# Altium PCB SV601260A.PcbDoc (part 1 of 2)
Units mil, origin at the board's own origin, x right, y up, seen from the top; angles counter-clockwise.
Board outline 2250 x 2132 mil, 4 copper layers (Top Layer, GND, POWER, Bottom Layer), stack 59.6 mil thick; 105 components, 61 nets, 262 pads, 157 vias.
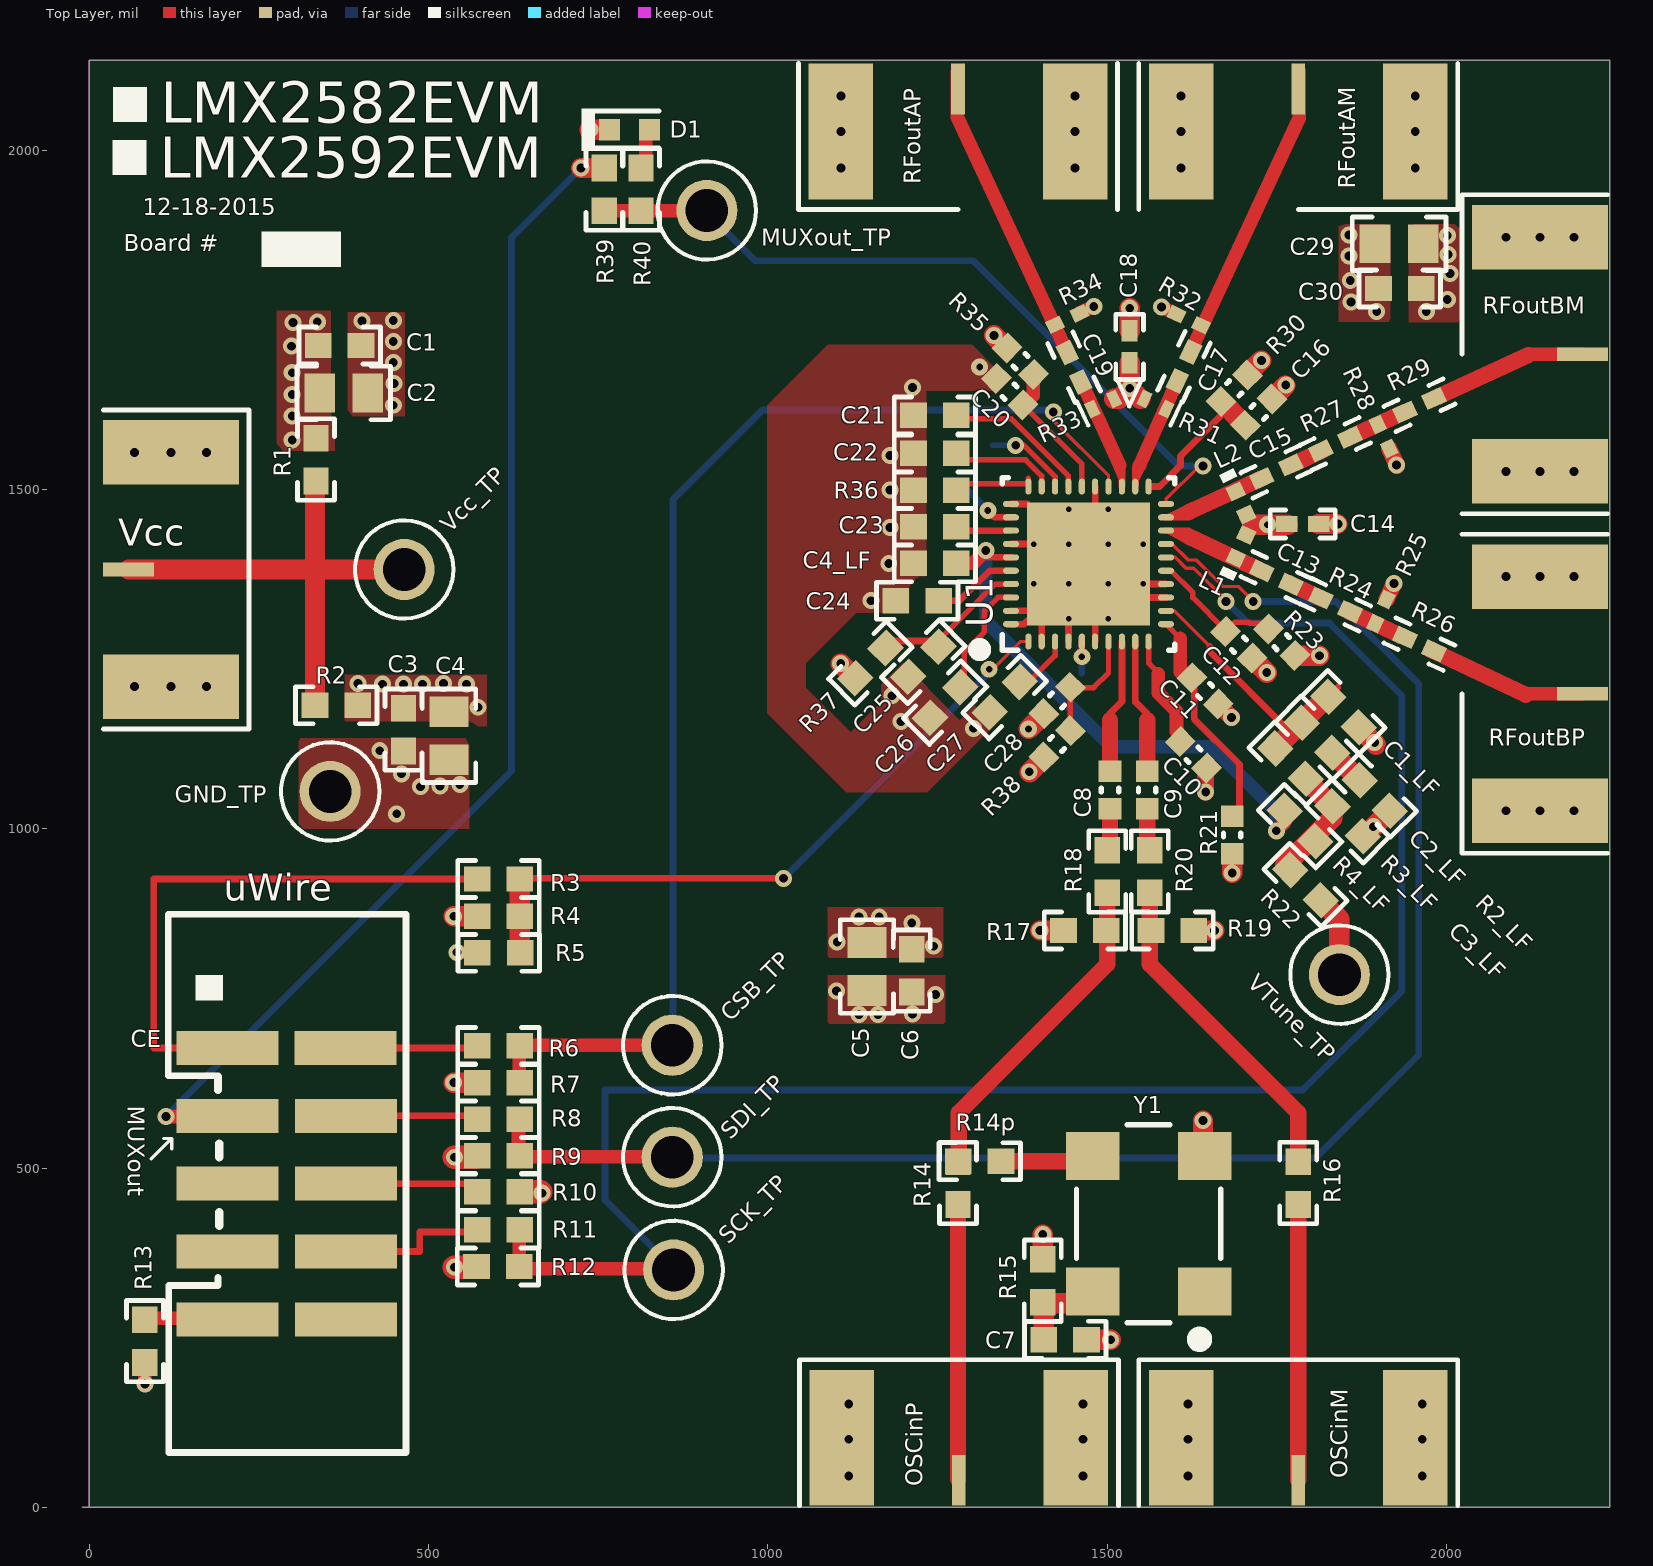
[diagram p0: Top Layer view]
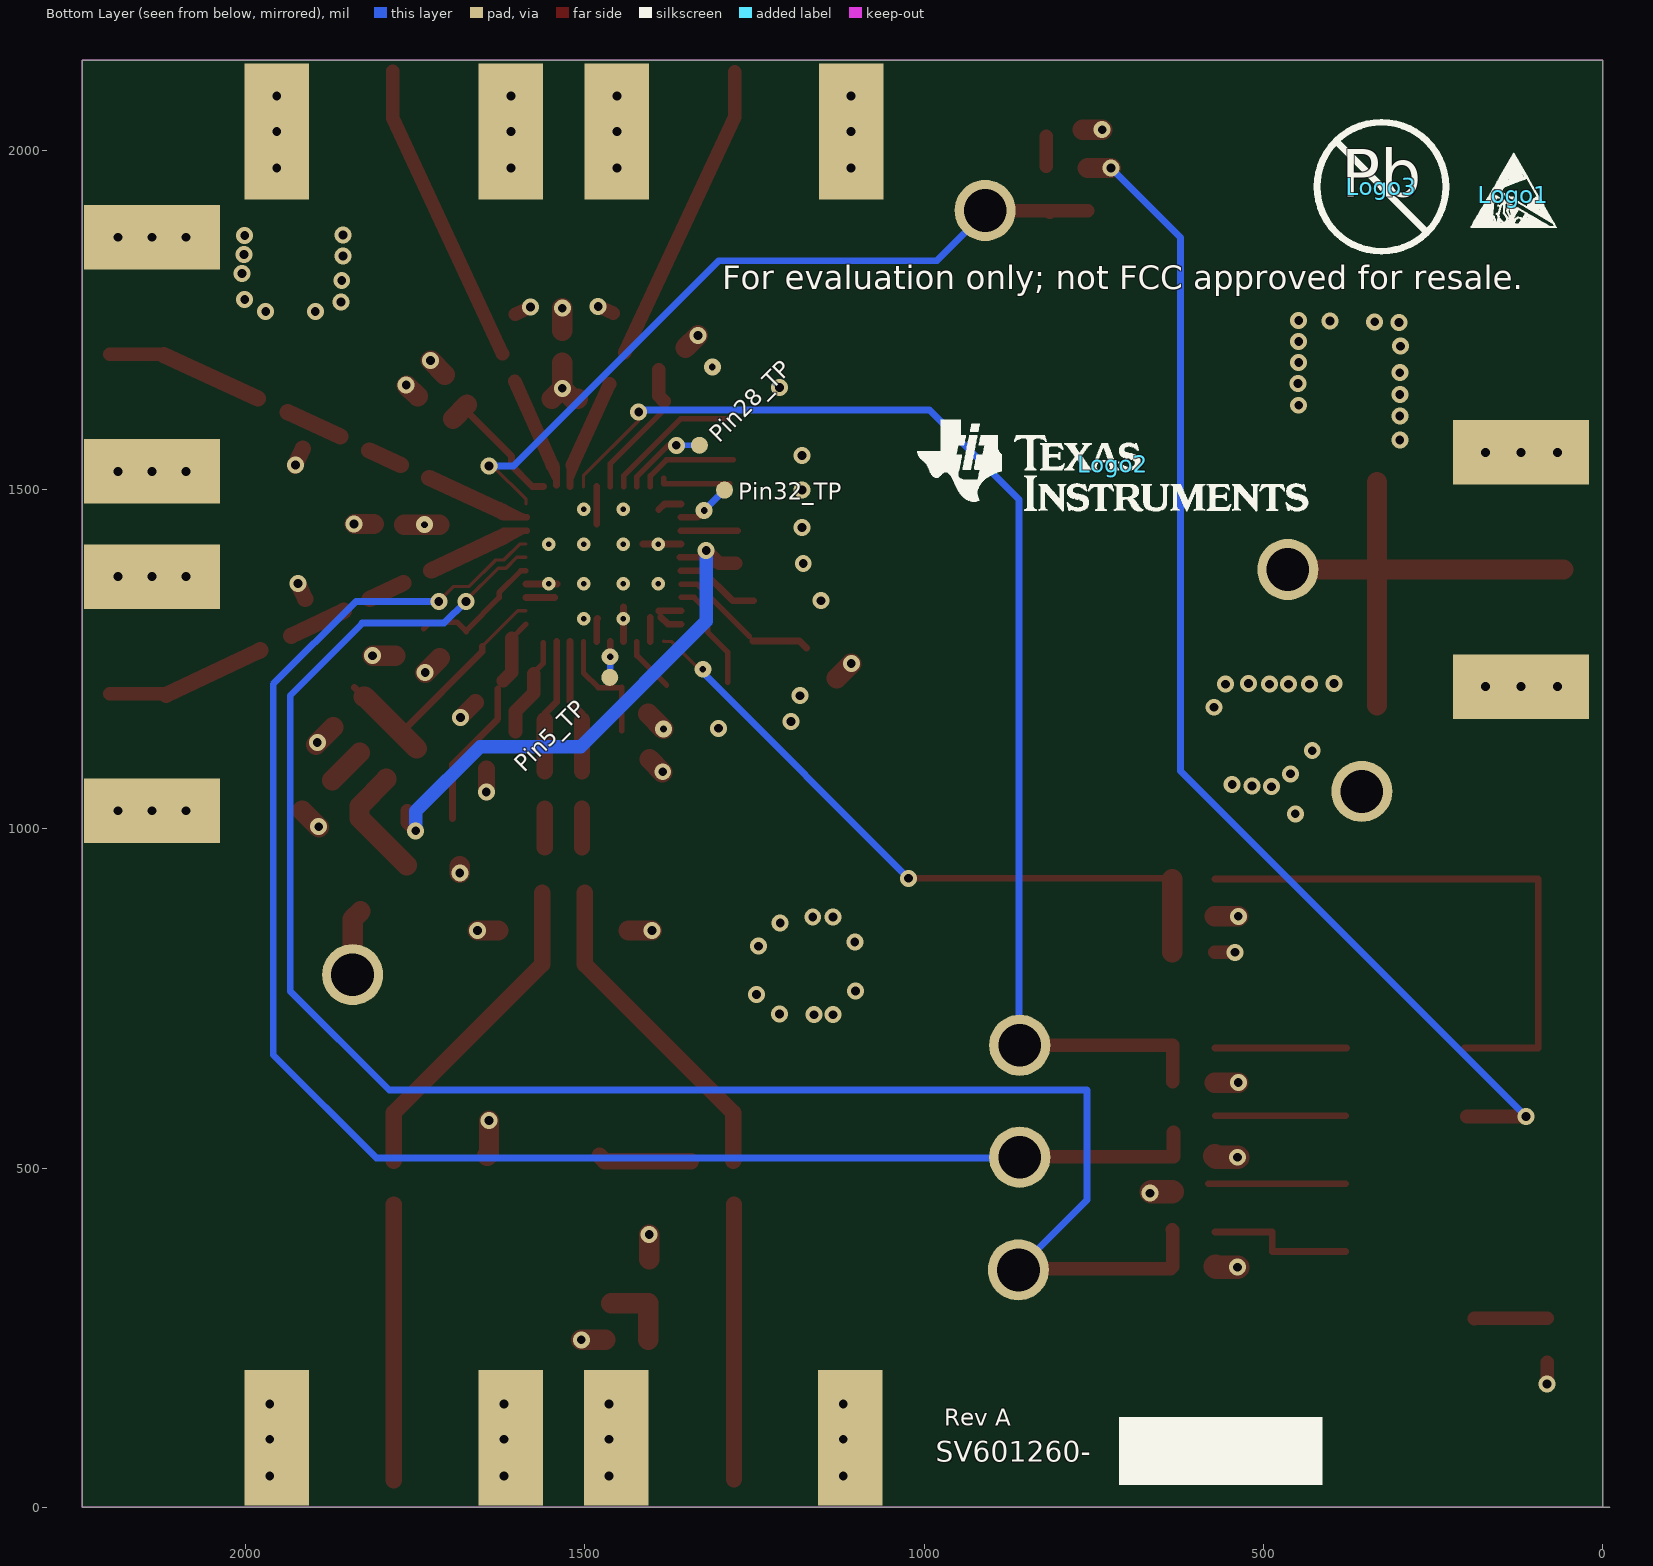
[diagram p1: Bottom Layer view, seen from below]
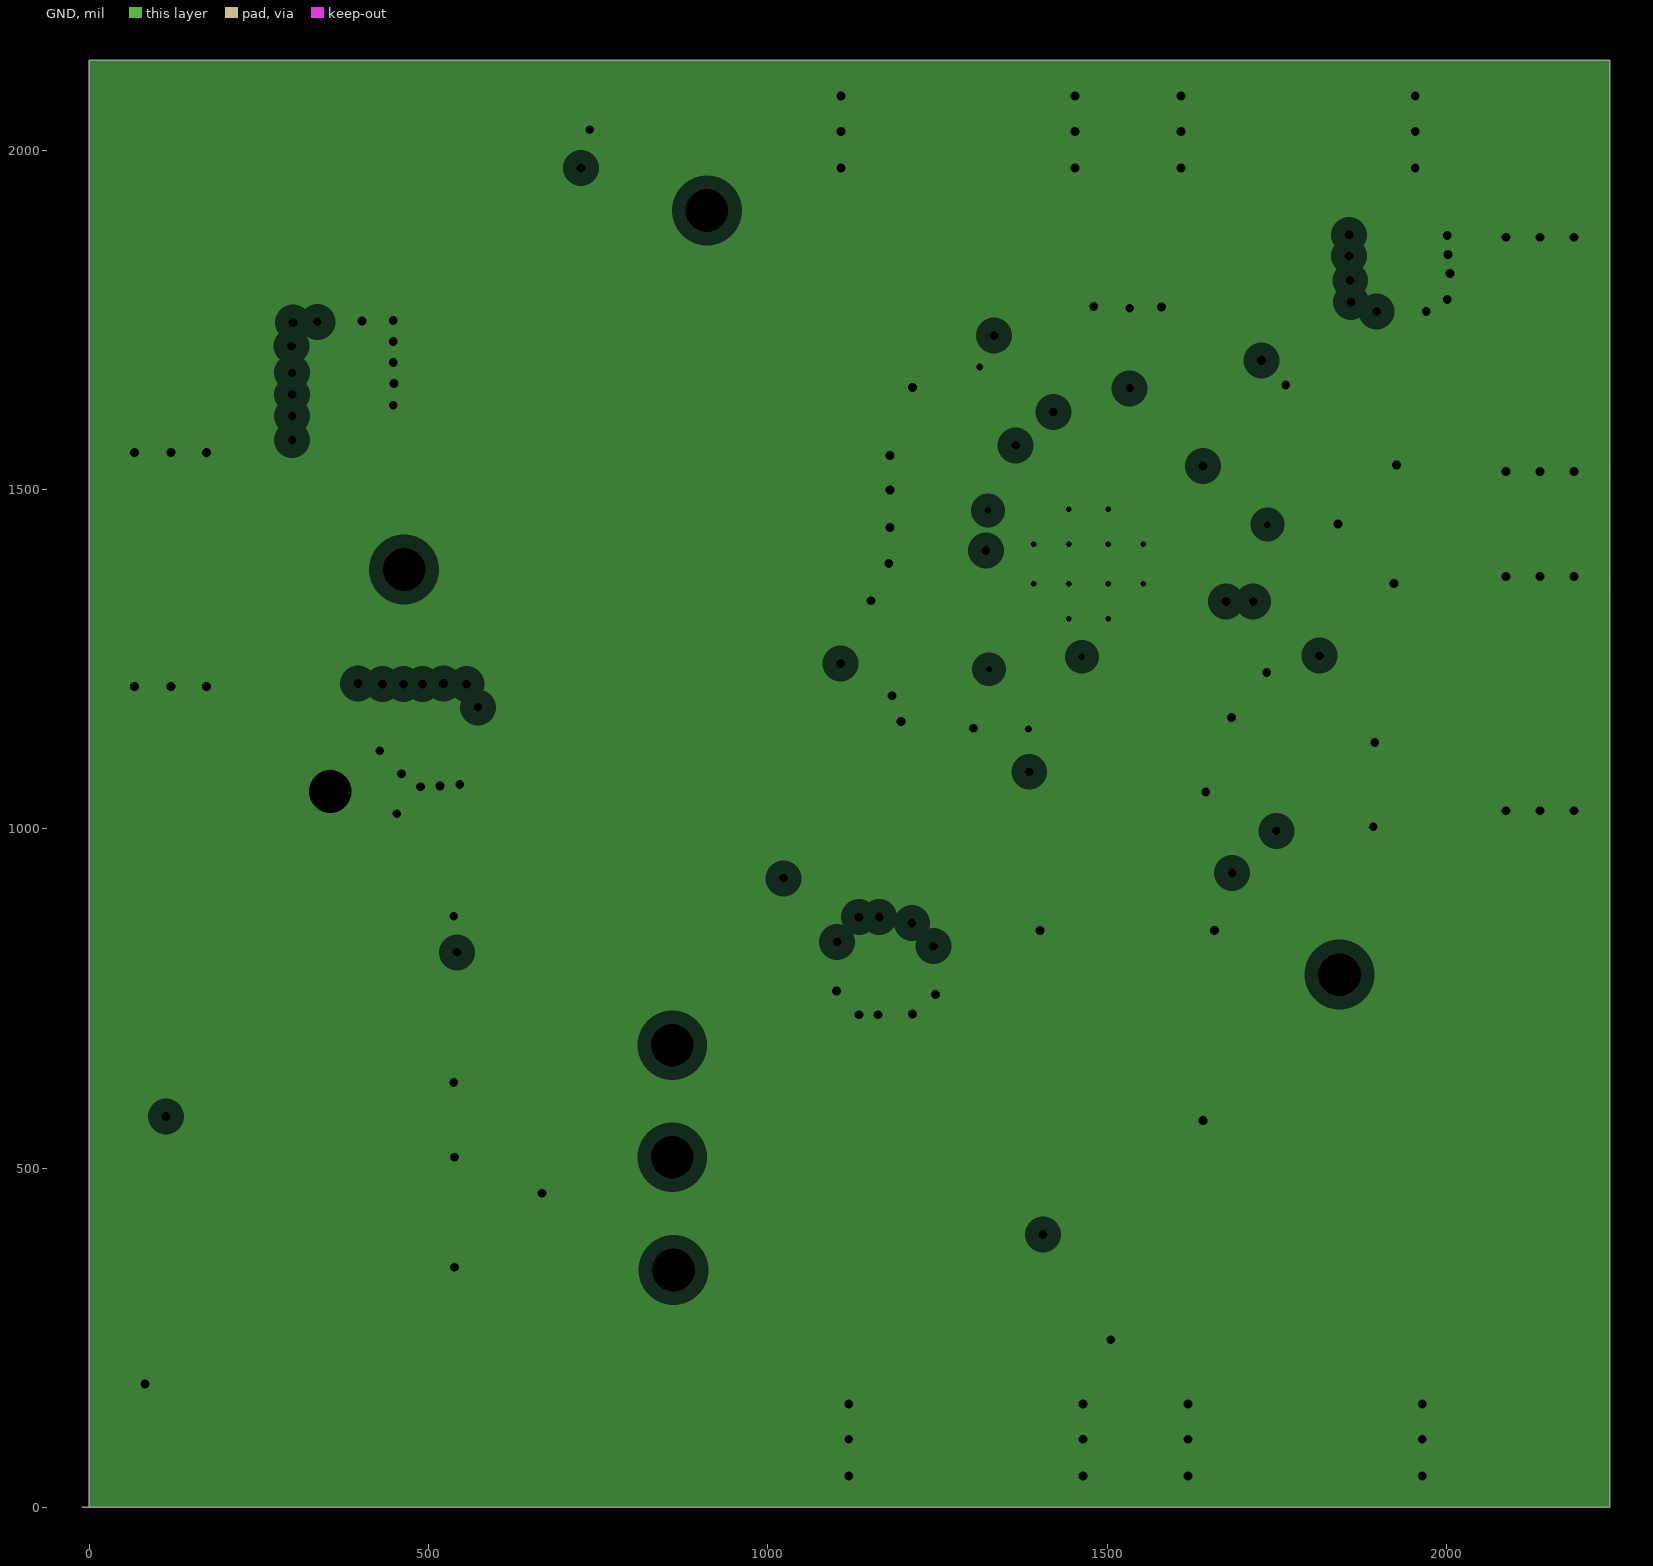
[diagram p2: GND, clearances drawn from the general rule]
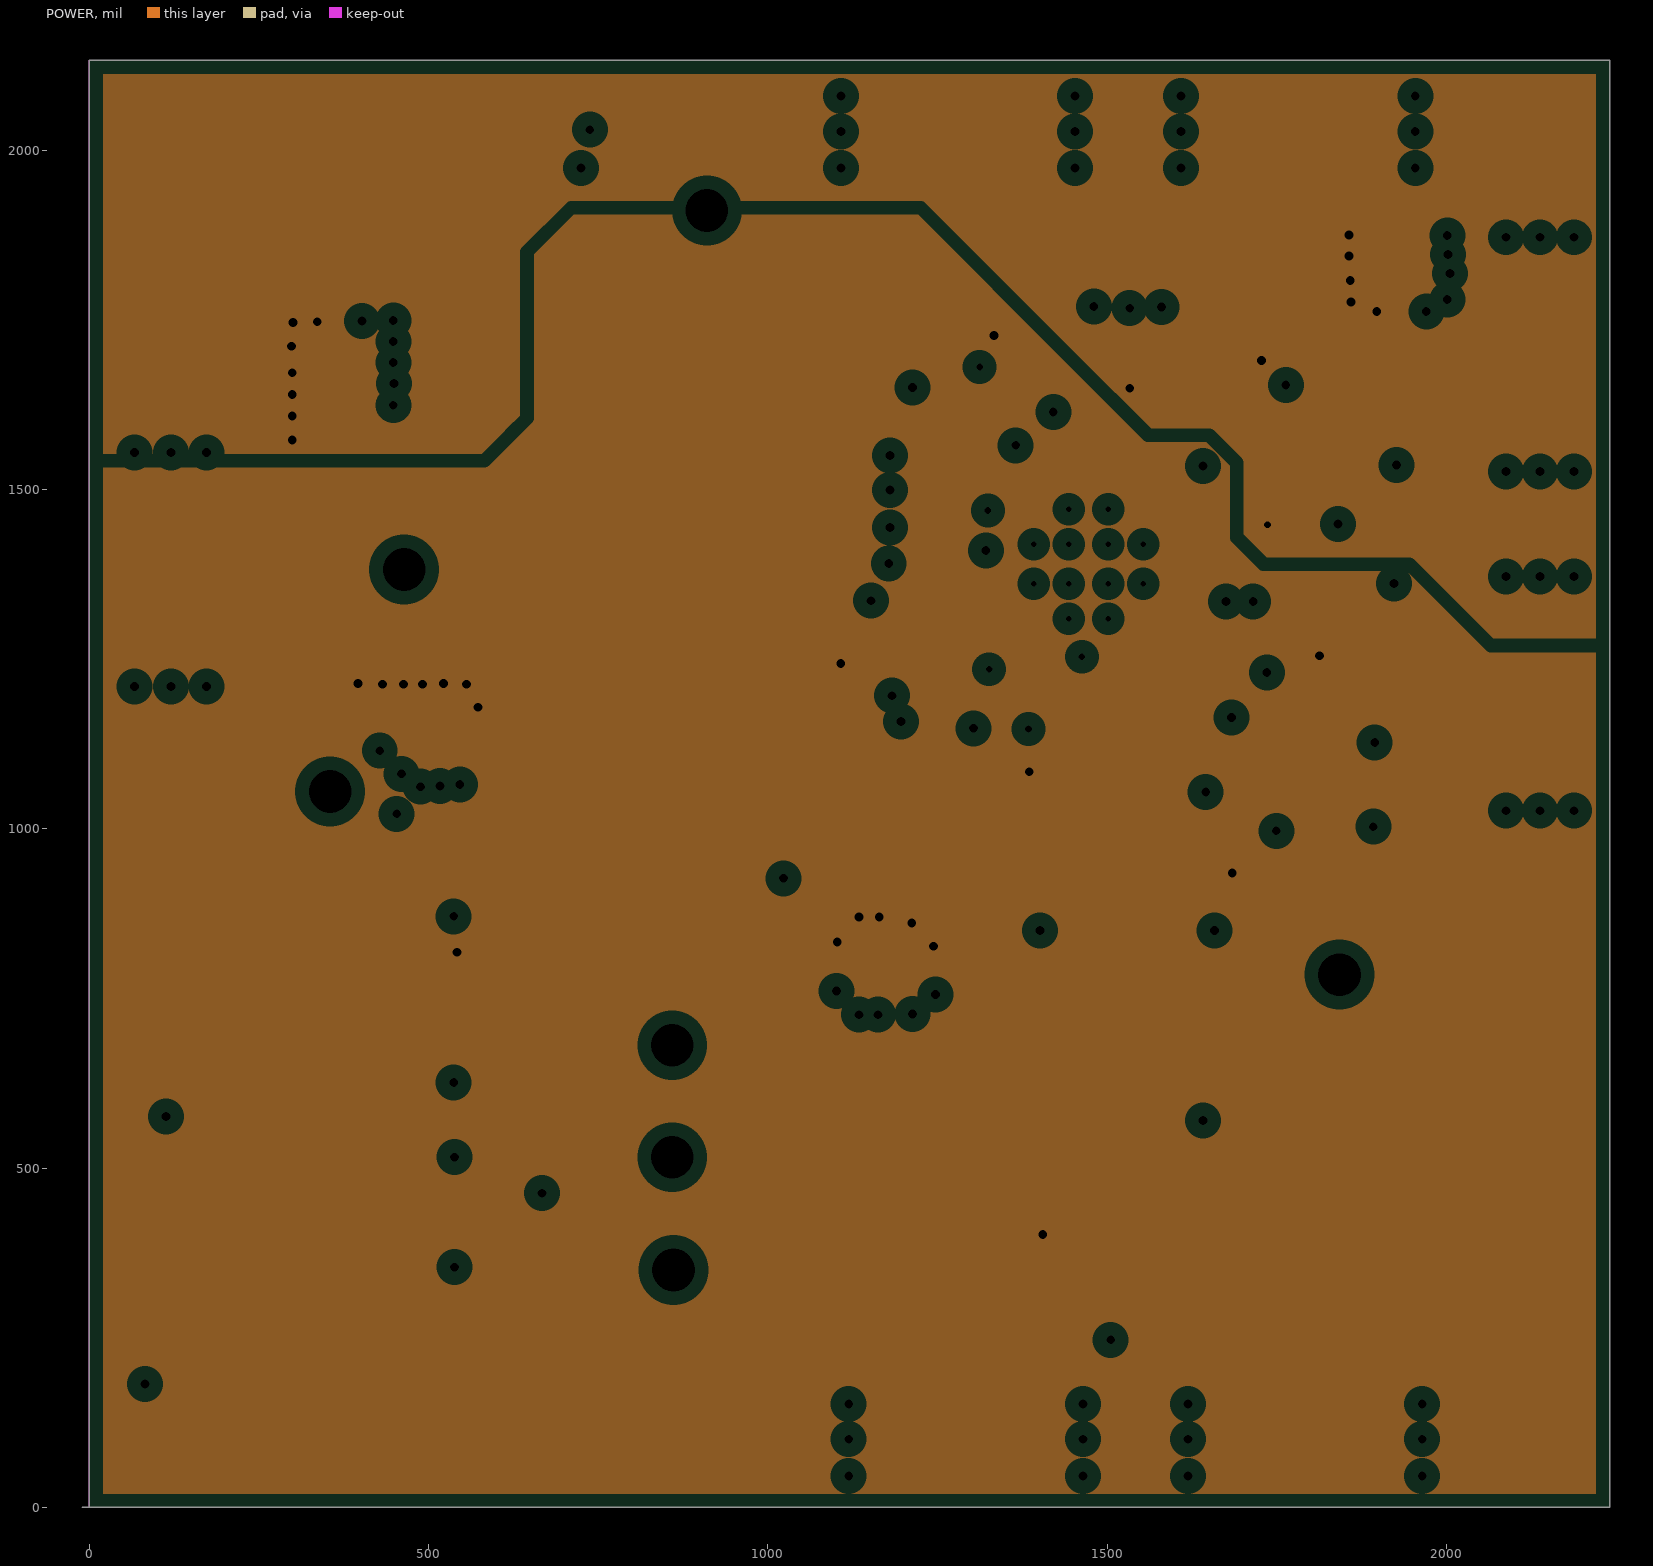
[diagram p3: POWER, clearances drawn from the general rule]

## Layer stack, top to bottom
Top Solder: solder mask 0.4, Solder Resist, Dk 3.5
Top Layer: signal copper 1.4
Dielectric1: core 9.5, Rogers4003C, Dk 4.8
GND: plane copper 1.4, net GND
Dielectric2: prepreg 35, FR-4, Dk 4.8
POWER: plane copper 1.4, net (Multiple Nets)
Dielectric3: core 9.5, FR-4, Dk 4.8
Bottom Layer: signal copper 1.4
Bottom Solder: solder mask 0.4, Solder Resist, Dk 3.5

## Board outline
2240,0 -10,0 0,0 0,2132 2240,2132 2240,0

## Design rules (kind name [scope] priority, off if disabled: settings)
AcuteAngle [All] p1: minimum=4.50000000000000E+0001 checktracksonly=FALSE
AssemblyTestPointUsage [All] p1: valid=2
Clearance Clearance_BoardEdge_MountingHoles [OnCopper and InComponentClass('Mounting Holes')] p1: gap=40
Clearance Clearance_1 [withinroom('BGA')] p2: gap=4
Clearance "pad TO PAD" [(InPadClass('All Pads')) vs (InPadClass('All Pads'))] p3: gap=7
Clearance Clearance_4 [ISPAD vs IsKeepOut] p4: gap=0
Clearance Clearance_2 [InPolygon vs InPolygon] p5: gap=25
Clearance Clearance_5 [InPolygon] p6: gap=15
Clearance [All] p7: gap=5
ComponentClearance ComponentClearance_Logo [InComponentClass('Logo')] p1: gap=50 collisioncheckmode=3 verticalgap=10 showdistances=FALSE
ComponentClearance ComponentClearance_ScrewToNut [(HasFootprint('NY PMS 440 0025 PH')) vs (HasFootprint('Keystone_1902C'))] p2: gap=5 collisioncheckmode=3 verticalgap=10 showdistances=FALSE
ComponentClearance ComponentClearance_MountingHoles [InComponentClass('Mounting Holes')] p3: gap=250 collisioncheckmode=3 verticalgap=100000 showdistances=FALSE
ComponentClearance ComponentClearance_SmallPassives [HasFootprint('0201*') or HasFootprint('0402*') or HasFootprint('0508') or HasFootprint('0603*') or HasFootprint('0612') or HasFootprint('0805*') or HasFootprint('0815*') or HasFootprint('0830*') or HasFootprint('1206*') or HasFootprint('1210*') or HasFootprint('1808*') or HasFootprint('1812*') or HasFootprint('1825*') or HasFootprint('2010*') or HasFootprint('2220*') or HasFootprint('2225*') or HasFootprint('2512*') or HasFootprint('2728*') or HasFootprint('3518*') vs HasFootprint('0201*') or HasFootprint('0402*') or HasFootprint('0508') or HasFootprint('0603*') or HasFootprint('0612') or HasFootprint('0805*') or HasFootprint('0815*') or HasFootprint('0830*') or HasFootprint('1206*') or HasFootprint('1210*') or HasFootprint('1808*') or HasFootprint('1812*') or HasFootprint('1825*') or HasFootprint('2010*') or HasFootprint('2220*') or HasFootprint('2225*') or HasFootprint('2512*') or HasFootprint('2728*') or HasFootprint('3518*')] p4: gap=5 collisioncheckmode=3 verticalgap=10 showdistances=FALSE
ComponentClearance ComponentClearance_THtoSMT [IsThruComponent vs IsSMTComponent] p5: gap=13 collisioncheckmode=3 verticalgap=30 showdistances=FALSE
ComponentClearance ComponentClearance_THtoTH [IsThruComponent vs IsThruComponent] p6: gap=13 collisioncheckmode=3 verticalgap=30 showdistances=FALSE
ComponentClearance [All] p7: gap=8 collisioncheckmode=3 verticalgap=10 showdistances=FALSE
DiffPairsRouting [All] p1: maxlimit=100 minlimit=10 mostfreqgap=10 toplayer_minwidth=15 toplayer_maxwidth=15 toplayer_prefwidth=15 bottomlayer_minwidth=15 bottomlayer_maxwidth=15 bottomlayer_prefwidth=15 maxuncoupledlength=1000
FabricationTestPointUsage TestPointUsage [All] p1: valid=2 allowmultiple=FALSE
FabricationTestpoint Testpoint [All] p1: side=3 testpointundercomponent=TRUE minsize=40 maxsize=100 preferedsize=60 minholesize=0 maxholesize=40 preferedholesize=32 testpointgrid=1 allowsidetop=TRUE allowsidebottom=TRUE usegrid=TRUE gridtolerance=0.01
FanoutControl Fanout_LCC [IsLCC] p1: bgadir=Out bgaviamode=Centered fanoutstyle=Auto fanoutdirection=Alternating viagrid=1 // Fanout_LCC (Default Rule)
FanoutControl Fanout_BGA [IsBGA] p2: bgadir=Out bgaviamode=Centered fanoutstyle=Auto fanoutdirection=Alternating viagrid=1 // Fanout_BGA (Default Rule)
FanoutControl Fanout_Default [All] p4: bgadir=Out bgaviamode=Centered fanoutstyle=Auto fanoutdirection=Alternating viagrid=1 // Fanout_Default (Default Rule)
FanoutControl Fanout_Small [(CompPinCount < 5)] p5: bgadir=Out bgaviamode=Centered fanoutstyle=Auto fanoutdirection=OutThenIn viagrid=1 // Fanout_Small (Default Rule)
HoleSize [All] p1: absolutevalues=TRUE maxlimit=251 minlimit=7.8 maxpercent=80.000 minpercent=20.000
MinimumAnnularRing MinimumAnnularRing_ThermalPadVias [IsVia and InAnyComponent] p1: minimumring=5.91
MinimumAnnularRing [All] p2: minimumring=6
MinimumSolderMaskSliver MinimumSolderMaskSliver_Logo [InComponentClass('Logo') vs InComponentClass('Logo')] p1: minsoldermaskwidth=0.7
MinimumSolderMaskSliver [All] p2: minsoldermaskwidth=0.2
PlaneClearance PlaneClearance_1 [withinroom('RF2')  or withinroom('RFvia_1')] p1: clearance=12
PlaneClearance [All] p2: clearance=20
PlaneConnect [All] p1: planeconnectstyle=Direct reliefexpansion=10 reliefentries=4 reliefconductorwidth=10 reliefairgap=10
PolygonConnect PolygonConnect-pad [ispad] p1: connectstyle=Direct reliefconductorwidth=15 reliefentries=4 polygonreliefangle="90 Angle" airgapwidth=10
PolygonConnect PolygonConnect-via [isvia] p2: connectstyle=Direct reliefconductorwidth=10 reliefentries=4 polygonreliefangle="90 Angle" airgapwidth=10
RoutingVias [All] p1: holewidth=13 width=25 viastyle="Through Hole" minholewidth=2 minwidth=5 maxholewidth=13 maxwidth=25
RoutingVias ThermalPadVias [IsVia and InAnyComponent] p2: holewidth=7.87 width=19.68 viastyle="Through Hole" minholewidth=2 minwidth=5 maxholewidth=12.99 maxwidth=23.62
SMDToCorner [All] p1: distance=30000
SilkToSilkClearance [All] p1: silktosilkclearance=0
SilkToSolderMaskClearance SilkscreenOverComponentPads [IsPad] p1: minsilkscreentomaskgap=0.9 clearancetoexposedcopper=TRUE
SolderMaskExpansion [All] p1: expansion=1.97
UnpouredPolygon [All] p1: allowunpoured=FALSE
Width 50ohm [InNetClass('50OHM')] p1: maxlimit=50 minlimit=8 preferedwidth=20
Width [All] p2: maxlimit=200 minlimit=5 preferedwidth=5 checkconnectedcopper=TRUE
14 further rules are at their usual default settings.

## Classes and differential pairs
component class Logo: Logo2
component class Header: uWire

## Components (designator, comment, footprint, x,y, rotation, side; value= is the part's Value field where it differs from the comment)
C1 "0603YC104JAT2A" 0603#1 369,1712 r180 top
C1_LF "C0603C561K5RACTU" 0603#1 1848,1172 r315 top
C2 "C0805C106K8PACTU" 0805 375,1642 r180 top
C2_LF "GRM188R71H473KA61D" 0603#1 1809,1134 r315 top
C3 "0603YC104JAT2A" 0603#1 463,1146 r90 top
C3_LF "GRM1885C2A301JA01D" 0603#1 1854,1011 r315 top
C4 "C0805C106K8PACTU" 0805 530,1137 r90 top
C4_LF "GRM188R71H682KA01D" 0603#2 1246,1391 r0 top
C5 "C0805C106K8PACTU" 0805 1146,797 r90 top
C6 "0603YC104JAT2A" 0603#1 1212,791 r90 top
C7 "C1608X7R1C105K" 0603#1 1438,247 r0 top
C8 "0603YC104JAT2A" 0603L 1504,1057 r90 top
C9 "0603YC104JAT2A" 0603L 1558.68,1057 r90 top
C10 "C1608X7R1C105K" 0603L 1627,1109 r135 top
C11 "0603YC104JAT2A" 0603L 1644,1203 r135 top
C12 "0603YC104JAT2A" 0603L 1694,1271 r135 top
C13 "GRM1535C1H101JDD5D" 0402#1 1749,1370 r155 top
C14 "GRM1535C1H101JDD5D" 0402#1 1788,1449.06 r180 top
C15 "GRM1535C1H101JDD5D" 0402#1 1749,1526 r205 top
C16 "0603YC104JAT2A" 0603L 1723,1614 r225 top
C17 "GRM1535C1H101JDD5D" 0402#1 1613,1681 r245 top
C18 "GRM1535C1H101JDD5D" 0402#2 1533,1710 r270 top
C19 "GRM1535C1H101JDD5D" 0402#1 1451,1680 r295 top
C20 "0603YC104JAT2A" 0603L 1356,1644 r315 top
C21 "C1608X5R1A106M" 0603#2 1246,1609 r180 top
C22 "C1608X5R1A106M" 0603#2 1246,1553 r180 top
C23 "C1608X5R1A106M" 0603#2 1246,1445 r180 top
C24 "C1608X5R1A106M" 0603#2 1220,1336 r180 top
C25 "0603YC104JAT2A" 0603#2 1229,1246 r45 top
C26 "C1608X5R0J105K" 0603#2 1261,1186 r225 top
C27 "C1608X5R1A106M" 0603#1 1349,1194 r45 top
C28 "0603YC104JAT2A" 0603L 1426,1189 r225 top
C29 "C0805C106K8PACTU" 0805 1930,1862 r180 top
C30 "0603YC104JAT2A" 0603#1 1931,1796 r180 top
CSB_TP "5007" Keystone5007 859,681 r270 top
D1 "LTST-C190GKT" LED_LTST-C190 796,2030 r180 top
GND_TP "5007" Keystone5007 355,1055 r270 top
L1 "LQG15HS18NJ02D" IND_LQG15H 1697,1416 r65 top
L2 "LQG15HS18NJ02D" IND_LQG15H 1697,1480 r295 top
Logo1 "ESD Susceptible" ESD_Overlay_Small 132,1934 r180 bottom
Logo2 "Texas Instruments" TI_Stacked_Overlay_Small_Vertical 722,1537 r270 bottom
Logo3 "Pb-Free Symbol" Pb-Free_Overlay_Medium 326,1946 r180 bottom
Logo4 "FCC disclaimer" FCC_disclaimer -500.95,693 r90 bottom
MUXout_TP "5007" Keystone5007 910,1911 r0 top
OSCinM "142-0701-851" EMERSON_142-0701-851 1781.34,40 r180 top
OSCinP "142-0701-851" EMERSON_142-0701-851 1281.34,40 r180 top
Pin5_TP "TESTPOINT" TP_25MIL-SMT 1463,1223 r90 bottom
Pin28_TP "TESTPOINT" TP_25MIL-SMT 1331,1565 r90 bottom
Pin32_TP "TESTPOINT" TP_25MIL-SMT 1294,1499 r90 bottom
R1 "CRCW06030000Z0EA" 0603#1 334,1544 r90 top
R2 "CRCW06030000Z0EA" 0603#1 364,1182 r0 top
R2_LF "CRCW0603150RJNEA" 0603#1 1894,1049 r315 top
R3 "CRCW060312K0JNEA" 0603#1 603,926 r0 top
R3_LF "CRCW060312R0JNEA" 0603#1 1770,1096 r315 top
R4 "CRCW060312K0JNEA" 0603#1 603,871 r0 top
R4_LF "CRCW06030000Z0EA" 0603#1 1784,1004 r315 top
R5 "CRCW060312K0JNEA" 0603#1 603.34,817.19 r0 top
R6 "CRCW060312K0JNEA" 0603#1 603,680 r0 top
R7 "CRCW060312K0JNEA" 0603#1 603,626 r0 top
R8 "CRCW060312K0JNEA" 0603#1 603,572 r180 top
R9 "CRCW060312K0JNEA" 0603#1 603,518 r0 top
R10 "CRCW06030000Z0EA" 0603#1 603,465 r180 top
R11 "CRCW060312K0JNEA" 0603#1 603,409 r0 top
R12 "CRCW060312K0JNEA" 0603#1 602,355 r0 top
R13 "CRCW06030000Z0EA" 0603#1 82,245 r270 top
R14 "CRCW060318R0JNEA" 0603#1 1280,478 r90 top
R14p "CRCW060318R0JNEA" 0603#1 1312,510 r0 top
R15 "CRCW060310R0JNEA" 0603#1 1405,334 r90 top
R16 "CRCW060318R0JNEA" 0603#1 1781.34,478 r90 top
R17 "CRCW060368R0JNEA" 0603#1 1467,850 r180 top
R18 "CRCW060318R0JNEA" 0603#1 1500,937 r90 top
R19 "CRCW060368R0JNEA" 0603#1 1596,850 r180 top
R20 "CRCW060318R0JNEA" 0603#1 1562.68,937 r270 top
R21 "CRCW06030000Z0EA" 0603L 1684,991 r90 top
R22 "CRCW06030000Z0EA" 0603#2 1792,917 r315 top
R23 "CRCW06030000Z0EA" 0603L 1757,1275 r135 top
R24 "CRCW040218R0JNED" 0402#2 1836,1330 r155 top
R25 "CRCW040268R0JNED" 0402L#1 1903,1320 r245 top
R26 "CRCW040218R0JNED" 0402#2 1960,1272 r155 top
R27 "CRCW040218R0JNED" 0402#2 1836,1567 r205 top
R28 "CRCW040268R0JNED" 0402L#1 1907,1578 r295 top
R29 "CRCW040218R0JNED" 0402#2 1960,1624 r205 top
R30 "CRCW06030000Z0EA" 0603L 1687,1649 r225 top
R31 "CRCW040249R9FKED" 0402L#2 1571,1626 r155 top
R32 "CRCW040249R9FKED" 0402L#1 1620,1750 r155 top
R33 "CRCW040249R9FKED" 0402L#2 1494,1626 r205 top
R34 "CRCW040249R9FKED" 0402L#1 1441,1751 r205 top
R35 "CRCW06030000Z0EA" 0603L 1372,1689 r135 top
R36 "RC0603FR-07680RL" 0603#2 1246,1499 r180 top
R37 "CRCW06030000Z0EA" 0603#2 1151,1244 r225 top
R38 "CRCW06030000Z0EA" 0603L 1426,1125 r45 top
R39 "CRCW06030000Z0EA" 0603#1 759,1942 r270 top
R40 "RC0603JR-07330RL" 0603#1 813,1942 r270 top
RFoutAM "142-0701-851" EMERSON_142-0701-851 1781.34,2090 r0 top locked
RFoutAP "142-0701-851" EMERSON_142-0701-851 1280,2090 r0 top locked
RFoutBM "142-0701-851" EMERSON_142-0701-851 2200,1699.06 r270 top
RFoutBP "142-0701-851" EMERSON_142-0701-851 2200,1199.06 r270 top
SCK_TP "5007" Keystone5007 861,350 r270 top
SDI_TP "5007" Keystone5007 859,516 r270 top
U1 "LMX2582RHAR" RHA0040C 1472.28,1390 r90 top
uWire "52601-S10-8LF" FCI_52601-S10-8LF 291,477 r0 top
Vcc "142-0701-851" EMERSON_142-0701-851 58,1382 r90 top
Vcc_TP "5007" Keystone5007 464,1382 r90 top
VTune_TP "5007" Keystone5007 1842,785 r0 top (schematic designator Vtune_TP)
Y1 "CWX813-100.0M" OSC_CWX 1561,418 r180 top

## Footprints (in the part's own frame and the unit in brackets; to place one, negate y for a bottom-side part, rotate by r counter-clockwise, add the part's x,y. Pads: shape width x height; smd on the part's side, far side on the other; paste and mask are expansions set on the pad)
0402#1 [mm] "0402 from SM-752 data"
  rect 0.8x0.6 smd mask+0: 1(-0.6,0) 2(0.6,0)
  silkscreen extent -1.22,-0.52 1.22,0.52, body extent -0.55,-0.3 0.55,0.3, height 0.6
0402#2 [mm] "0402 from SM-752 data"
  rect 0.8x0.6 smd: 1(-0.6,0) 2(0.6,0)
  silkscreen extent -1.22,-0.52 1.22,0.52, body extent -0.55,-0.3 0.55,0.3, height 0.6
0402L#1 [mm] "0402 from SM-752 data"
  rect 0.6x0.5 smd: 1(-0.5,0) 2(0.5,0)
  body extent -0.55,-0.3 0.55,0.3, height 0.6
0402L#2 [mm] "Chip Capacitor, Body 1.0x0.5mm, IPC High Density"
  rect 0.4x0.6 smd mask+0: 1(-0.45,0) 2(0.45,0)
  silkscreen extent -0.85,-0.5 0.85,0.5, body extent -0.55,-0.3 0.55,0.3, height 1.3
0603#1 [mm] "0603 from SM-752 data"
  rect 1x0.95 smd mask+0: 1(-0.8,0) 2(0.8,0)
  silkscreen extent -1.52,-0.69 1.52,0.69, body extent -0.87,-0.47 0.87,0.47, height 0.85
0603#2 [mm] "0603 from SM-752 data"
  rect 1x0.95 smd: 1(-0.8,0) 2(0.8,0)
  silkscreen extent -1.52,-0.69 1.52,0.69, body extent -0.87,-0.47 0.87,0.47, height 0.85
0603L [mm] "0603 from SM-752 data"
  rect 0.8x0.85 smd: 1(-0.7,0) 2(0.7,0)
  silkscreen extent -0.07,-0.33 0.07,0.33, body extent -0.87,-0.47 0.87,0.47, height 0.85
0805 [mm] "0805"
  rect 1.15x1.45 smd mask+0: 1(-0.9,0) 2(0.9,0)
  silkscreen extent -1.75,-1 1.75,1, body extent -1.1,-0.72 1.1,0.72, height 1.1
EMERSON_142-0701-851 [mil] "Johnson Components"
  rect 20x75 smd mask+0: 1(0,0)
  rect 95x200 smd mask+0: 2(-172.5,-62.5) 3(172.5,-62.5)
  rect 95x200 smd far side mask+0: 4(172.5,-62.5) 5(-172.5,-62.5)
  silkscreen extent -235,-178 235,38, body extent -190,-158 190,424, height 155
ESD_Overlay_Small [mil]
  silkscreen extent -62,-48 64,61
FCC_disclaimer [mil]
FCI_52601-S10-8LF [mil] "FCI Electronics"
  rect 150x50 smd mask+0: 1(-87.5,200) 2(86.5,200) 3(-87.5,100) 4(87.5,100) 5(-87.5,0) 6(87.5,0) 7(-87.5,-100) 8(87.5,-100) 9(-87.5,-200) 10(87.5,-200)
  silkscreen extent -175,-396 176,397, body extent -173,-395 172,395, height 496
IND_LQG15H [mm] "MuRata"
  rect 0.55x0.6 smd: 1(-0.475,0) 2(0.475,0)
  silkscreen extent -1.3,-0.3 -0.95,0.3, body extent -0.52,-0.27 0.52,0.27, height 0.55
Keystone5007 [mil]
  round 90 hole 63 mask+0: 1(0,0)
  silkscreen extent -72,-72 72,72
LED_LTST-C190 [mm] "Lite-On"
  rect 0.8x0.8 smd: 1(-0.75,0) 2(0.75,0)
  silkscreen extent -1.1,-0.8 1.8,0.8, body extent -0.85,-0.45 0.85,0.45, height 0.9
OSC_CWX [mm] "CONNOR WINFIELD"
  rect 2x1.8 smd mask+0: 1(-2.1,2.54) 2(-2.1,-2.54) 3(2.1,-2.54) 4(2.1,2.54)
  silkscreen extent -2.7,-3.7 2.7,4.55, body extent -2.65,-3.65 2.65,3.65, height 1.31
Pb-Free_Overlay_Medium [mil]
  silkscreen extent -95,-95 95,95
RHA0040C [mm] "QFN, 40-Leads, Body 6x6mm, Pitch 0.5mm, Thermal Pad 4.6 x 4.6mm, TI Recommended"
  oval 0.6x0.23 smd: 1(-2.9,2.25) 2(-2.9,1.75) 3(-2.9,1.25) 4(-2.9,0.75) 5(-2.9,0.25) 6(-2.9,-0.25) 7(-2.9,-0.75) 8(-2.9,-1.25) 9(-2.9,-1.75) 10(-2.9,-2.25) 21(2.9,-2.25) 22(2.9,-1.75) 23(2.9,-1.25) 24(2.9,-0.75) 25(2.9,-0.25) 26(2.9,0.25) 27(2.9,0.75) 28(2.9,1.25) 29(2.9,1.75) 30(2.9,2.25)
  oval 0.23x0.6 smd: 11(-2.25,-2.9) 12(-1.75,-2.9) 13(-1.25,-2.9) 14(-0.75,-2.9) 15(-0.25,-2.9) 16(0.25,-2.9) 17(0.75,-2.9) 18(1.25,-2.9) 19(1.75,-2.9) 20(2.25,-2.9) 31(2.25,2.9) 32(1.75,2.9) 33(1.25,2.9) 34(0.75,2.9) 35(0.25,2.9) 36(-0.25,2.9) 37(-0.75,2.9) 38(-1.25,2.9) 39(-1.75,2.9) 40(-2.25,2.9)
  rect 4.6x4.6 smd paste-2.5: 41(0,0)
  silkscreen extent -3.22,-3.22 3.22,3.22, body extent -3.08,-3.08 3.08,3.08, height 1.01
TI_Stacked_Overlay_Small_Vertical [mil]
  silkscreen extent -66,-288 69,288
TP_25MIL-SMT [mil]
  round 25 smd mask-2.5: 1(0,0)

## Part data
C1 C3 C6 C8 C9 C11 C12 C16 C20 C25 C28 C30: "CAP, CERM, 0.1uF, 16V, +/-5%, X7R, 0603"
C1_LF: "CAP, CERM, 560 pF, 50 V, +/- 10%, X7R, 0603"
C2 C4 C5 C29: "CAP, CERM, 10uF, 10V, +/-10%, X5R, 0805"
C2_LF: "CAP, CERM, 0.047 µF, 50 V, +/- 10%, X7R, 0603"
C3_LF: "CAP, CERM, 300pF, 100V, +/-5%, C0G/NP0, 0603"
C4_LF: "CAP, CERM, 6800 pF, 50 V, +/- 10%, X7R, 0603"
C7 C10: "CAP, CERM, 1uF, 16V, +/-10%, X7R, 0603"
C13 C14 C15 C17 C18 C19: "CAP, CERM, 100 pF, 50 V, +/- 5%, C0G/NP0, 0402"
C21 C22 C23 C24 C27: "CAP, CERM, 10uF, 10V, +/-10%, C0G/NP0, 0603"
C26: "CAP, CERM, 1 µF, 6.3 V, +/- 10%, X5R, 0603"
CSB_TP GND_TP MUXout_TP SCK_TP SDI_TP Vcc_TP VTune_TP: "Test Point, Compact, White, TH"
D1: "LED, Green, SMD"
L1 L2: "Inductor, Multilayer, Air Core, 18 nH, 0.3 A, 0.36 ohm, SMD"
Logo1: library part ESD_Susceptible, "ESD Susceptible Symbol"
Logo2: library part TI_Logo, "Texas Instrument Corporate Signature"
Logo3: library part Pb-Free
Logo4: library part FCC_disclaimer, "FCC_disclaimer"
OSCinM OSCinP RFoutAM RFoutAP RFoutBM RFoutBP Vcc: "Connector, SMT, End launch SMA 50 ohm"
Pin5_TP Pin28_TP Pin32_TP: "TEST POINT.  No entry in BOM."
R1 R2 R4_LF R10 R13 R21 R22 R23 R30 R35 R37 R38 R39: "RES, 0 ohm, 5%, 0.1W, 0603"
R2_LF: "RES, 150, 5%, 0.1 W, 0603"
R3 R4 R5 R6 R7 R8 R9 R11 R12: "RES, 12k ohm, 5%, 0.1W, 0603"
R3_LF: "RES, 12, 5%, 0.1 W, 0603"
R14 R14p R16 R18 R20: "RES, 18 ohm, 5%, 0.1W, 0603"
R15: "RES, 10 ohm, 5%, 0.1W, 0603"
R17 R19: "RES, 68 ohm, 5%, 0.1W, 0603"
R24 R26 R27 R29: "RES, 18, 5%, 0.063 W, 0402"
R25 R28: "RES, 68, 5%, 0.063 W, 0402"
R31 R32 R33 R34: "RES, 49.9, 1%, 0.063 W, 0402"
R36: "RES, 680, 1%, 0.1 W, 0603"
R40: "RES, 330 ohm, 5%, 0.1W, 0603"
U1: "High Performance, Wideband PLLatinum RF Synthesizer, RHA0040C"
uWire: "Header (shrouded), 100mil, 5x2, Gold plated, SMD"
Y1: "OSC 100.0000MHZ 3.3V +-25PPM SMD"

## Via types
v1: diameter 25, hole 13, Top Layer to Bottom Layer, tented both sides, 74 vias
v2: diameter 25, hole 13, Top Layer to Bottom Layer, 65 vias
v3: diameter 19.68, hole 7.87, Top Layer to Bottom Layer, 12 vias
v4: diameter 25, hole 10, Top Layer to Bottom Layer, 6 vias

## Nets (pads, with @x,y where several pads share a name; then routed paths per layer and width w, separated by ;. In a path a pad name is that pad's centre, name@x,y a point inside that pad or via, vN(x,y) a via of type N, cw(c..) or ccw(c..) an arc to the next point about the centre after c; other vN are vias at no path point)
GND: C1.1 C1_LF.2 C2.1 C3.1 C3_LF.2 C4.1 C4_LF.1 C5.1 C6.1 C7.2 C10.1 C11.1 C12.1 C14.1 C16.1 C18.1 C20.1 C21.2 C22.2 C23.2 C24.2 C25.1 C26.2 C27.1 C28.2 C29.1 C30.1 D1.2 GND_TP.1 OSCinM.2 OSCinM.3 OSCinM.4 OSCinM.5 OSCinP.2 OSCinP.3 OSCinP.4 OSCinP.5 R2_LF.2 R4.1 R7.1 R9.1 R10.1 R12.1 R13.2 R17.2 R19.1 R25.1 R28.2 R32.2 R34.1 R36.2 RFoutAM.2 RFoutAM.3 RFoutAM.4 RFoutAM.5 RFoutAP.2 RFoutAP.3 RFoutAP.4 RFoutAP.5 RFoutBM.2 RFoutBM.3 RFoutBM.4 RFoutBM.5 RFoutBP.2 RFoutBP.3 RFoutBP.4 RFoutBP.5 U1.2 U1.4 U1.6 U1.13 U1.14 U1.25 U1.31 U1.34 U1.39 U1.40 U1.41 Vcc.2 Vcc.3 Vcc.4 Vcc.5 Y1.2 | length 1190.2
  Top Layer w10: U1.40@1358.11,1301.42 1377.42,1301.42 U1.41@1388,1312 ; U1.39@1358.11,1321.1 1390.9,1321.1 U1.41@1391,1321 ; U1.34@1358.11,1419.53 U1.41@1414.47,1419.53 ; U1.31@1358.11,1478.58 1382.42,1478.58 U1.41@1391,1470 ; U1.2@1403.39,1275.83 U1.41@1403.39,1311.61 ; U1.4@1442.76,1275.83 U1.41@1442.76,1326.76 ; U1.41@1481,1310 1482.13,1308.87 U1.6@1482.13,1275.83 ; U1.41@1482.13,1449.13 U1.25@1482.13,1504.17 ; U1.41@1540.53,1360.47 U1.14@1586.46,1360.47 ; U1.41@1544.21,1340.79 U1.13@1586.46,1340.79
  Top Layer w20: v1(82,182) R13.2@82,214 ; R34.1@1457.84,1759.32 v2(1480.13,1769.71) ; v2(1579.87,1768.71) R32.2@1602.16,1758.32
  Top Layer w24: R25.1@1911.81,1338.43 v2(1922.55,1361.21) ; R28.2@1915.54,1559.85 v2@1927,1535
  Top Layer w25: v1(1645,1054) C10.1@1645,1088 ; C11.1@1660.81,1186.19 v2(1683,1164)
  Top Layer w30: v2(537,626) R7.1@571.5,626 ; v2(537,871) R4.1@571.5,871 ; v2(737.53,2030) D1.2@766,2030 ; v4(1384,1147) C28.2@1406.51,1169.51 ; v1(1401,850) R17.2@1435.5,850 ; C7.2@1469.5,247 v2(1505,247) ; C18.1@1533,1734 v2(1533,1767) ; R19.1@1627.5,850 v1(1658,850) ; v2(1641,570) 1641,520.68 Y1.2@1643.68,518 ; C12.1@1713.49,1251.51 v2(1735,1230) ; C16.1@1746,1637 v1@1762,1653 ; C14.1@1810.62,1449 v1@1839,1449 ; C1_LF.2@1870.27,1149.73 v2@1896,1124 ; v2@1891.54,1002 R2_LF.2@1916.27,1026.73
  Top Layer w35: v2(538,354) 569.5,354 R12.1@570.5,355 ; v2(538,516) 569.5,516 R9.1@571.5,518 ; R10.1@634.5,465 v2@665,465
  other v1: 1119,46.5 1619,46.5 1464,46.5 1964,46.5 1119,100.5 1619,100.5 1464,100.5 1964,100.5 1119,152.5 1619,152.5 1464,152.5 1964,152.5 1162,726 1213,727 2087.5,1026.56 2137.5,1026.56 2187.5,1026.56 517,1063 546,1065 460,1081 66.5,1209.5 120.5,1209.5 172.5,1209.5 2087.5,1371.56 2137.5,1371.56 2187.5,1371.56 1840,1449 2087.5,1526.56 2137.5,1526.56 2187.5,1526.56 66.5,1554.5 120.5,1554.5 172.5,1554.5 448,1624 1763,1654 449,1656 448,1718 2087.5,1871.56 2137.5,1871.56 2187.5,1871.56 1107.5,1973.5 1608.84,1973.5 1953.84,1973.5 1452.5,1973.5 1107.5,2027.5 1608.84,2027.5 1953.84,2027.5 1452.5,2027.5 1107.5,2079.5 1608.84,2079.5 1953.84,2079.5 1452.5,2079.5
  other v2: 667,463 1134,726 1247,756 1101,761 1892,1003 453,1022 488,1062 428,1115 1894,1127 1303.04,1148.04 1196,1158 1183,1196 1152,1336 1178,1391 1180,1444 1180,1499 1926,1536 1180,1550 1213,1650 448,1687 402,1748 448,1749 1970,1762 2001,1780 2005,1818 2002,1846 2001,1874
  other v3: 1443.17,1309.29 1501.4,1309.29 1391.58,1360.89 1443.17,1360.89 1501.4,1360.89 1552.99,1360.89 1391.58,1419.11 1443.17,1419.11 1501.4,1419.11 1552.99,1419.11 1443.17,1470.71 1501.4,1470.71
  other v4: 1312,1680.49
MUXOUT: R39.1 uWire.3 | length 1772.3
  Top Layer w20: v2(113,576) uWire.3@200,576
  Top Layer w30: v2(724.5,1973.5) R39.1@759,1973.5
  Bottom Layer w10: v2(113,576) 622,1085 622,1870.99 v2(724.5,1973.5)
NetC1_LF_1: C1_LF.1 C2_LF.1 R3_LF.1 U1.12 | length 388.5
  Top Layer w5: U1.12@1586.46,1321.1 1598.9,1321.1 1651,1269
  Top Layer w10: 1651,1269 1651,1261 1768,1144 ; C1_LF.1@1825.73,1194.27 1839.46,1208
  Top Layer w30: R3_LF.1@1747.73,1118.27 1823.73,1194.27 C1_LF.1@1825.73,1194.27
NetC2_LF_2: C2_LF.2 R2_LF.1 | length 57.2
  Top Layer w30: C2_LF.2@1831.27,1111.73 R2_LF.1@1871.73,1071.27
NetC3_LF_1: C3_LF.1 R3_LF.2 R4_LF.2 R22.1 | length 173
  Top Layer w30: R22.1@1762,946 1831.73,1015.73 C3_LF.1@1831.73,1033.27 1792.27,1072.73 R3_LF.2@1792.27,1073.73
NetC4_LF_2: C4_LF.2 R4_LF.1 U1.35 | length 811.9
  Top Layer w10: 1311,1400 U1.35@1360,1400
  Top Layer w20: C4_LF.2@1277.5,1391 1302,1391 1311,1400 v2(1321,1410) ; v2(1749,997) 1761.73,1009.73 R4_LF.1@1761.73,1026.27
  Bottom Layer w20: v2(1321,1410) 1321,1321 1321,1306 1506,1121 1654,1121 1749,1026 v2(1749,997)
NetC7_1: C7.1 R15.1 Y1.4 | length 108.8
  Top Layer w30: C7.1@1406.5,247 1406.5,301 Y1.4@1461.32,301
NetC8_1: C8.1 R18.2 | length 56.9
  Top Layer w24: R18.2@1504,972.5 C8.1@1504,1029.44
NetC8_2: C8.2 U1.8 | length 188.5
  Top Layer w10: 1504,1170 1521.5,1187.5 U1.8@1521.5,1275.83
  Top Layer w24: C8.2@1504,1084.56 1504,1160
NetC9_1: C9.1 R20.1 | length 56.9
  Top Layer w24: R20.1@1558.68,972.5 C9.1@1558.68,1029.44
NetC9_2: C9.2 U1.9 | length 188.5
  Top Layer w10: 1541.18,1187.5 U1.9@1541.18,1275.83 ; 1541.5,1186.5 1559,1169
  Top Layer w24: C9.2@1558.68,1084.56 1558.68,1160
NetC10_2: C10.2 U1.10 | length 138.8
  Top Layer w8: U1.10@1560.87,1273.86 1560.87,1244.13 1570,1235
  Top Layer w20: 1575,1228 1575,1200 1602,1173 C10.2@1602,1143
NetC11_2: C11.2 R21.2 U1.11 | length 316.1
  Top Layer w8: U1.11@1586.46,1301.42 1607.5,1280.37
  Top Layer w10: C11.2@1628,1206 1628,1162 1695,1095 R21.2@1695,1015
  Top Layer w20: 1607.5,1280.37 1607.5,1230.5 C11.2@1620.01,1217.99
NetC12_2: C12.2 R23.2 U1.15 | length 203.5
  Top Layer w8: U1.15@1586.46,1380.16 1593.98,1380.16 1626,1348.14 1626,1340.61 1674.51,1292.1 C12.2@1674.51,1290.49 1688.47,1304.44 1708.56,1304.44 1710,1303 1729,1303 R23.2@1737.51,1294.49
NetC13_1: C13.1 R24.2 | length 55
  Top Layer w24: C13.1@1767,1362 R24.2@1816.78,1338.52
NetC13_2: C13.2 L1.1 U1.18 | length 190.1
  Top Layer w9.05: U1.18@1585,1439 1620,1439 ; U1.18@1591,1438 1623,1421
  Top Layer w24: 1618.49,1431.26 C13.2@1726,1380.56
NetC15_1: C15.1 R27.2 | length 51
  Top Layer w24: C15.1@1771,1536 R27.2@1817.3,1557.35
NetC15_2: C15.2 L2.1 U1.19 | length 196
  Top Layer w9.05: U1.19@1585,1459 1620,1459 ; U1.19@1591.72,1460.54 1624,1477 ; 1606,1461 1611.38,1463.51
  Top Layer w24: 1621,1467 C15.2@1728.95,1516.77
NetC16_2: C16.2 R30.2 U1.21 | length 205.6
  Top Layer w10: U1.21@1560.87,1504.17 1577.27,1504.17 1608,1534.9 1608,1549 1673.49,1614.49 R30.2@1673.49,1624.51
  Top Layer w30: R30.2@1673.49,1624.51 C16.2@1694,1604
NetC17_1: C17.1 R32.1 RFoutAM.1 | length 452.1
  Top Layer w20: C17.1@1621.11,1699.82 1783,2047 RFoutAM.1@1783,2116
NetC17_2: C17.2 R31.1 U1.22 | length 185
  Top Layer w9.05: 1544,1517 1553.9,1536.57
  Top Layer w10: U1.22@1541.6,1506.08 1541.6,1532.93
  Top Layer w20: 1547.44,1535.25 C17.2@1602.95,1659.62
NetC19_1: C19.1 R34.2 RFoutAP.1 | length 449.5
  Top Layer w20: RFoutAP.1@1279.12,2115 1279.12,2048.59 C19.1@1441.02,1701.41
NetC19_2: C19.2 R33.2 U1.23 | length 185
  Top Layer w9.05: 1512.12,1536.33 1520.74,1516.16
  Top Layer w10: U1.23@1521.5,1504.17 1521.5,1535.63
  Top Layer w20: C19.2@1463.46,1655.29 1518.19,1535.63
NetC20_2: C20.2 R35.1 U1.26 | length 199.3
  Top Layer w8: C20.2@1380,1620 1462.44,1537.56 U1.26@1462.44,1504.17
  Top Layer w20: C20.2@1383,1630 1391,1638 R35.1@1391,1676
NetC21_1: C21.1 U1.27 | length 205.4
  Top Layer w8: C21.1@1288,1604 1358.8,1604 1442.76,1520.04 U1.27@1442.76,1504.17
NetC22_1: C22.1 U1.29 | length 147.8
  Top Layer w8: C22.1@1281,1543.5 1379.7,1543.5 1403.39,1519.81 U1.29@1403.39,1504.17
NetC23_1: C23.1 U1.33 | length 83.1
  Top Layer w10: C23.1@1275,1439.21 U1.33@1358.11,1439.21
NetC24_1: C24.1 U1.36 | length 124.9
  Top Layer w10: C24.1@1251.5,1336 1282,1336 1326.16,1380.16 U1.36@1358.11,1380.16
NetC25_2: C25.2 R37.1 U1.37 | length 215.9
  Top Layer w8: C25.2@1257.5,1283.5 1334.47,1360.47 U1.37@1358.11,1360.47
  Top Layer w10: R37.1@1173.27,1266.27 1183.49,1276.49 C25.2@1252.49,1276.49
NetC26_1: C26.1 U1.38 | length 164.7
  Top Layer w8: C26.1@1289,1216 1289,1260 1319,1290 1319,1321 1338.79,1340.79 U1.38@1358.11,1340.79
NetC27_2: C27.2 U1.3 | length 82.4
  Top Layer w8: C27.2@1379.5,1211.5 1423.07,1255.07 U1.3@1423.07,1275.83
NetC28_1: C28.1 R38.2 U1.7 | length 175.4
  Top Layer w8: R38.2@1445.49,1144.49 C28.1@1445.49,1208 ; C28.1@1445.49,1208.49 C28.1@1445.49,1208 ; U1.7@1501.81,1275.83 1501.81,1229.81 1480,1208 C28.1@1445.49,1208
NetCSB_TP_1: CSB_TP.1 R6.2 R7.2 U1.24 | length 1842.4
  Top Layer w5: v1(1420.5,1614.2) 1420.5,1601.5 1501.81,1520.19 U1.24@1501.81,1504.17
  Top Layer w20: R7.2@633.5,627 633.5,681 CSB_TP.1@859,681
  Bottom Layer w10: CSB_TP.1@860,681 860,1485 992,1617 v1@1420.5,1617
NetD1_1: D1.1 R40.1 | length 44
  Top Layer w20: R40.1@820,1976.02 D1.1@820,2020
NetMUXout_TP_1: MUXout_TP.1 R39.2 R40.2 U1.20 | length 1123.2
  Top Layer w5: U1.20@1586.46,1478.58 1586.46,1485.26 1635.5,1534.3 v1(1641.2,1534.3)
  Top Layer w20: R39.2@759,1910.5 MUXout_TP.1@909.5,1910.5 ; R40.2@813,1910.5 R40.2@815,1908.5
  Bottom Layer w10: MUXout_TP.1@908.5,1909.5 981,1837 1302,1837 1604.7,1534.3 v1(1641.2,1534.3)
NetOSCinM_1: OSCinM.1 R16.1 | length 406.5
  Top Layer w24: OSCinM.1@1781.34,40 R16.1@1781.34,446.5
NetOSCinP_1: OSCinP.1 R14.1 | length 405.2
  Top Layer w24: OSCinP.1@1280,41.34 R14.1@1280,446.5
